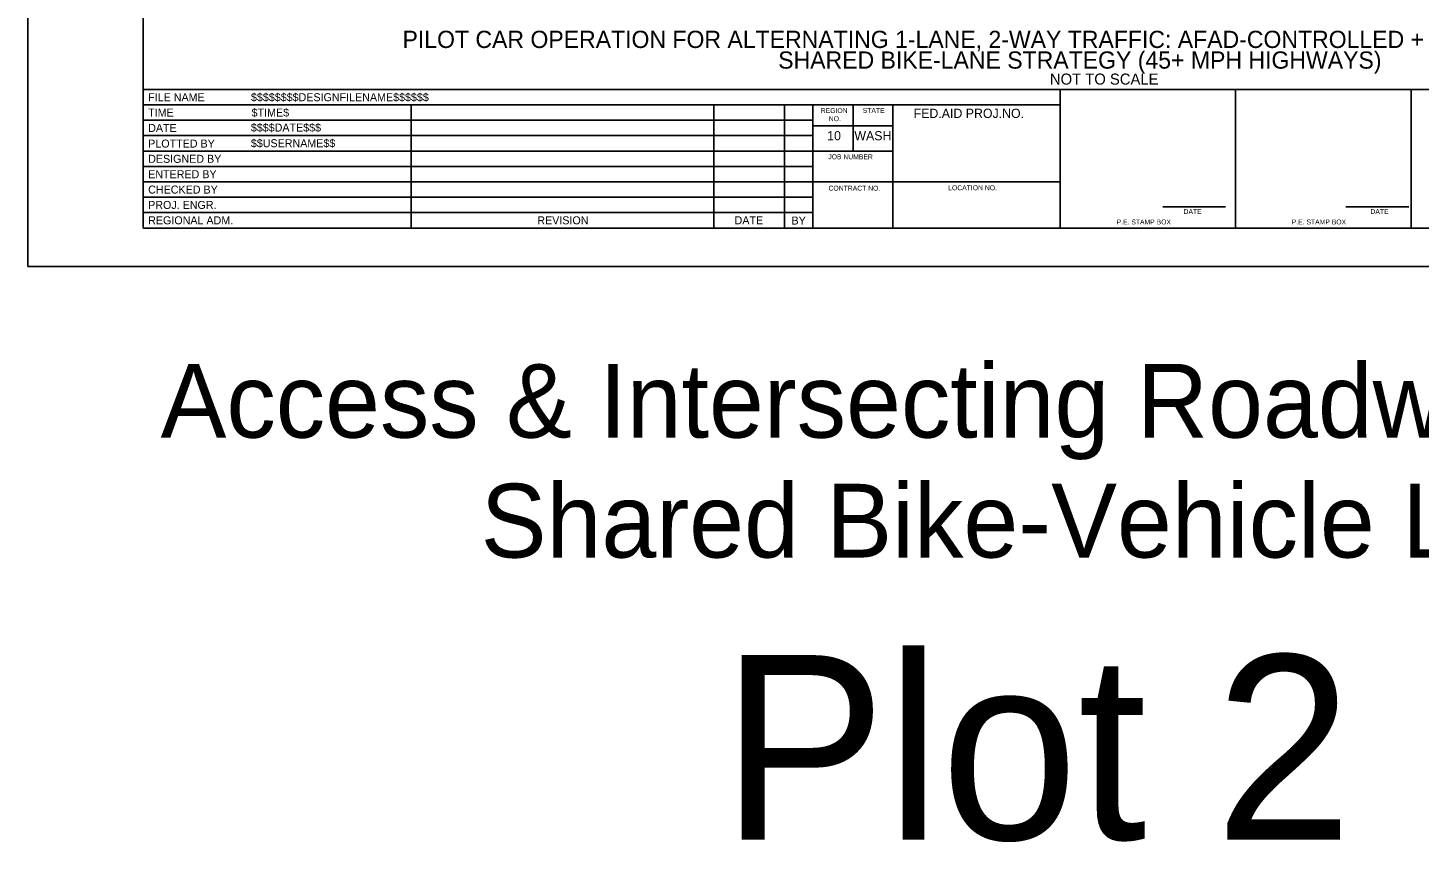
# Model space of a CAD drawing. Extents: x 99999.1 to 100095.7, y 99995 to 100010.7.
# Drawn here: x 100019.06 to 100030.38, y 99995.01 to 100001.63 of the extents above; entities that cross this region are included whole.
import ezdxf

# ---------------------------------------------------------------- set-up
doc = ezdxf.new("R2010")
doc.units = 0
for name, color, linetype in [('SH_DE_DetailHeading1Text', 7, 'Continuous'), ('SH_GI_PlotLimits', 7, 'Continuous'), ('SH_GI_SheetBorder', 7, 'Continuous'), ('SH_GI_SheetLocationText', 7, 'Continuous'), ('SH_GI_SheetTextInCells', 7, 'Continuous'), ('SH_GI_TitleBlockText', 7, 'Continuous')]:
    doc.layers.add(name, color=color, linetype=linetype)

msp = doc.modelspace()

# ---------------------------------------------------------------- linework, layer by layer
at = {"layer": 'SH_GI_PlotLimits'}
msp.add_lwpolyline([(100019.062, 99999.687), (100036.062, 99999.687), (100036.062, 100010.687), (100019.062, 100010.687)], close=True, dxfattribs=at)
at = {"layer": 'SH_GI_SheetBorder'}
for p, q in [((100020, 100010.375), (100020, 100000)), ((100020, 100001.126), (100035.75, 100001.126)), ((100027.457, 100000), (100027.457, 100001.126)), ((100028.883, 100000), (100028.883, 100001.126)), ((100030.309, 100001.126), (100030.309, 100000)), ((100020, 100001.001), (100027.457, 100001.001)), ((100022.179, 100001.001), (100022.179, 100000)), ((100024.641, 100001.001), (100024.641, 100000)), ((100025.216, 100001.001), (100025.216, 100000)), ((100025.445, 100001.001), (100025.445, 100000)), ((100025.772, 100000.625), (100025.772, 100001.001)), ((100026.096, 100000), (100026.096, 100001.001)), ((100020, 100000.876), (100022.182, 100000.876)), ((100022.182, 100000.876), (100025.447, 100000.876)), ((100026.096, 100000.831), (100025.447, 100000.831)), ((100020, 100000.751), (100022.182, 100000.751)), ((100022.182, 100000.751), (100025.447, 100000.751)), ((100020, 100000.625), (100025.447, 100000.625)), ((100026.096, 100000.625), (100025.447, 100000.625)), ((100020, 100000.5), (100025.447, 100000.5)), ((100020, 100000.375), (100025.447, 100000.375)), ((100027.457, 100000.375), (100025.447, 100000.375)), ((100020, 100000.25), (100025.447, 100000.25)), ((100020, 100000.125), (100025.447, 100000.125)), ((100028.29, 100000.173), (100028.802, 100000.173)), ((100029.78, 100000.173), (100030.291, 100000.173)), ((100020, 100000), (100035.75, 100000))]:
    msp.add_line(p, q, dxfattribs=at)

# ---------------------------------------------------------------- texts
at = {"layer": 'SH_DE_DetailHeading1Text'}
for s, height, p in [('PILOT CAR OPERATION FOR ALTERNATING 1-LANE, 2-WAY TRAFFIC: AFAD-CONTROLLED + TEMP. RUMBLE STRIPS', 0.14, (100022.109, 100001.464)), ('SHARED BIKE-LANE STRATEGY (45+ MPH HIGHWAYS)', 0.14, (100025.164, 100001.296)), ('NOT TO SCALE', 0.09, (100027.373, 100001.166))]:
    msp.add_text(s, height=height, rotation=360, dxfattribs=at).set_placement(p)
at = {"layer": 'SH_GI_SheetLocationText'}
for s, height, p in [('Access & Intersecting Roadway Details', 0.6, (100020.142, 99998.295)), ('Shared Bike-Vehicle Lane', 0.6, (100022.745, 99997.32)), ('Plot 2', 1.5, (100024.702, 99995.027))]:
    msp.add_text(s, height=height, dxfattribs=at).set_placement(p)
at = {"layer": 'SH_GI_SheetTextInCells'}
for s, height, p in [('FILE NAME', 0.0651, (100020.041, 100001.031)), ('TIME', 0.0651, (100020.041, 100000.906)), ('REGION', 0.04, (100025.51, 100000.935)), ('NO.', 0.04, (100025.575, 100000.869)), ('STATE', 0.04, (100025.851, 100000.936)), ('FED.AID PROJ.NO.', 0.07506, (100026.265, 100000.895)), ('DATE', 0.0651, (100020.041, 100000.781)), ('10', 0.0751, (100025.562, 100000.713)), ('WASH', 0.0751, (100025.783, 100000.713)), ('PLOTTED BY', 0.0651, (100020.041, 100000.654)), ('DESIGNED BY', 0.06505, (100020.041, 100000.53)), ('JOB NUMBER', 0.04, (100025.571, 100000.559)), ('ENTERED BY', 0.0651, (100020.041, 100000.405)), ('CHECKED BY', 0.0651, (100020.041, 100000.28)), ('CONTRACT NO.', 0.04003, (100025.573, 100000.304)), ('LOCATION NO.', 0.04003, (100026.546, 100000.307)), ('PROJ. ENGR.', 0.06505, (100020.041, 100000.155)), ('REGIONAL ADM.', 0.06505, (100020.041, 100000.03)), ('REVISION', 0.0651, (100023.205, 100000.03)), ('DATE', 0.04, (100028.46, 100000.114)), ('DATE', 0.04, (100029.979, 100000.114)), ('DATE', 0.0651, (100024.809, 100000.03)), ('BY', 0.0651, (100025.272, 100000.028)), ('P.E. STAMP BOX', 0.04003, (100027.915, 100000.029)), ('P.E. STAMP BOX', 0.04003, (100029.339, 100000.029))]:
    msp.add_text(s, height=height, dxfattribs=at).set_placement(p)
at = {"layer": 'SH_GI_TitleBlockText'}
for s, height, p in [('$$$$$$$$DESIGNFILENAME$$$$$$', 0.06505, (100020.877, 100001.031)), ('$TIME$', 0.0651, (100020.882, 100000.906)), ('$$$$DATE$$$', 0.06505, (100020.876, 100000.784)), ('$$USERNAME$$', 0.06505, (100020.876, 100000.657))]:
    msp.add_text(s, height=height, dxfattribs=at).set_placement(p)

doc.saveas('drawing.dxf')
